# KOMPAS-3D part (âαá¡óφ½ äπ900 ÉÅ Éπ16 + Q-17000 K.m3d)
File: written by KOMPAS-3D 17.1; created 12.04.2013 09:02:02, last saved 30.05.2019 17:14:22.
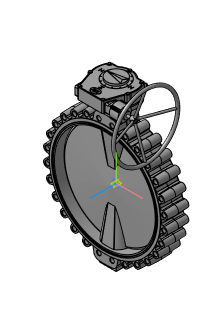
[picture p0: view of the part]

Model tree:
1. Операция без истории:3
